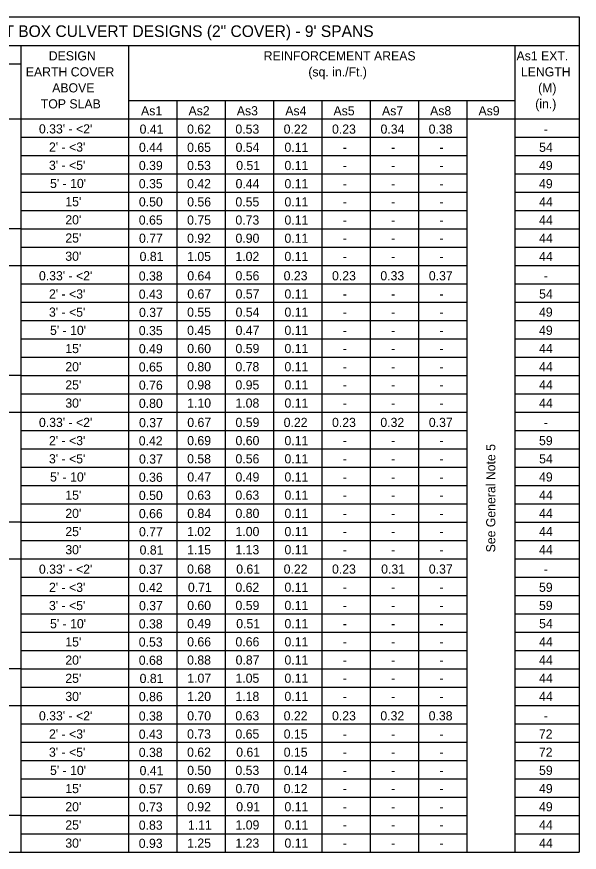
# Model space of a CAD drawing. Extents: x 10346.98 to 10349.19, y 76399.48 to 76400.59.
# Drawn here: x 10347.193 to 10347.579, y 76399.925 to 76400.5 of the extents above; entities that cross this region are included whole.
import ezdxf

# ---------------------------------------------------------------- set-up
doc = ezdxf.new("R2010")
doc.units = 0
doc.layers.add('AdhocPoint_dp', color=7, linetype='Continuous')
doc.layers.add('PlotBorder_dp', color=7, linetype='Continuous')

msp = doc.modelspace()

# ---------------------------------------------------------------- linework, layer by layer
at = {"layer": 'PlotBorder_dp'}
for p, q in [((10346.98451, 76400.49971), (10347.57925, 76400.49971)), ((10347.57925, 76400.49971), (10347.57925, 76399.92549)), ((10346.98451, 76400.47984), (10347.57925, 76400.47984)), ((10347.19559, 76400.47984), (10347.19559, 76399.92549)), ((10347.26947, 76400.47984), (10347.26947, 76399.92549)), ((10347.53506, 76400.47984), (10347.53506, 76399.92549)), ((10347.05314, 76400.46724), (10347.19559, 76400.46724)), ((10347.26947, 76400.44209), (10347.53506, 76400.44209)), ((10347.30267, 76400.44209), (10347.30267, 76399.92549)), ((10347.33586, 76400.44209), (10347.33586, 76399.92549)), ((10347.36906, 76400.44209), (10347.36906, 76399.92549)), ((10347.40226, 76400.44209), (10347.40226, 76399.92549)), ((10347.43546, 76400.44209), (10347.43546, 76399.92549)), ((10347.43546, 76400.44209), (10347.43546, 76399.92549)), ((10347.46866, 76400.44209), (10347.46866, 76399.92549)), ((10347.50186, 76400.44209), (10347.50186, 76399.92549)), ((10346.98451, 76400.42949), (10347.57925, 76400.42949)), ((10347.19559, 76400.41689), (10347.50186, 76400.41689)), ((10347.53506, 76400.41689), (10347.57925, 76400.41689)), ((10347.19559, 76400.40429), (10347.50186, 76400.40429)), ((10347.53506, 76400.40429), (10347.57925, 76400.40429)), ((10347.19559, 76400.39169), (10347.50186, 76400.39169)), ((10347.53506, 76400.39169), (10347.57925, 76400.39169)), ((10347.19559, 76400.37909), (10347.50186, 76400.37909)), ((10347.53506, 76400.37909), (10347.57925, 76400.37909)), ((10347.19559, 76400.36649), (10347.50186, 76400.36649)), ((10347.53506, 76400.36649), (10347.57925, 76400.36649)), ((10347.19559, 76400.35389), (10347.05314, 76400.35389)), ((10347.19559, 76400.35389), (10347.50186, 76400.35389)), ((10347.53506, 76400.35389), (10347.57925, 76400.35389)), ((10347.19559, 76400.34129), (10347.50186, 76400.34129)), ((10347.53506, 76400.34129), (10347.57925, 76400.34129)), ((10346.98451, 76400.32869), (10347.50186, 76400.32869)), ((10347.53506, 76400.32869), (10347.57925, 76400.32869)), ((10347.19559, 76400.31609), (10347.50186, 76400.31609)), ((10347.53506, 76400.31609), (10347.57925, 76400.31609)), ((10347.19559, 76400.30349), (10347.50186, 76400.30349)), ((10347.53506, 76400.30349), (10347.57925, 76400.30349)), ((10347.19559, 76400.29089), (10347.50186, 76400.29089)), ((10347.53506, 76400.29089), (10347.57925, 76400.29089)), ((10347.19559, 76400.27829), (10347.50186, 76400.27829)), ((10347.53506, 76400.27829), (10347.57925, 76400.27829)), ((10347.19559, 76400.26569), (10347.50186, 76400.26569)), ((10347.53506, 76400.26569), (10347.57925, 76400.26569)), ((10347.19559, 76400.25309), (10347.05314, 76400.25309)), ((10347.19559, 76400.25309), (10347.50186, 76400.25309)), ((10347.53506, 76400.25309), (10347.57925, 76400.25309)), ((10347.19559, 76400.24049), (10347.50186, 76400.24049)), ((10347.53506, 76400.24049), (10347.57925, 76400.24049)), ((10346.98451, 76400.22789), (10347.50186, 76400.22789)), ((10347.19621, 76400.22789), (10347.26838, 76400.22789)), ((10347.53506, 76400.22789), (10347.57925, 76400.22789)), ((10347.19559, 76400.21529), (10347.50186, 76400.21529)), ((10347.53506, 76400.21529), (10347.57925, 76400.21529)), ((10347.19559, 76400.20269), (10347.50186, 76400.20269)), ((10347.53506, 76400.20269), (10347.57925, 76400.20269)), ((10347.19559, 76400.19009), (10347.50186, 76400.19009)), ((10347.53506, 76400.19009), (10347.57925, 76400.19009)), ((10347.19559, 76400.17749), (10347.50186, 76400.17749)), ((10347.53506, 76400.17749), (10347.57925, 76400.17749)), ((10347.19559, 76400.16489), (10347.50186, 76400.16489)), ((10347.53506, 76400.16489), (10347.57925, 76400.16489)), ((10347.19559, 76400.15229), (10347.05314, 76400.15229)), ((10347.19559, 76400.15229), (10347.50186, 76400.15229)), ((10347.53506, 76400.15229), (10347.57925, 76400.15229)), ((10347.19559, 76400.13969), (10347.50186, 76400.13969)), ((10347.53506, 76400.13969), (10347.57925, 76400.13969)), ((10346.98451, 76400.12709), (10347.50186, 76400.12709)), ((10347.19621, 76400.12709), (10347.26838, 76400.12709)), ((10347.19621, 76400.12709), (10347.26838, 76400.12709)), ((10347.53506, 76400.12709), (10347.57925, 76400.12709)), ((10347.19559, 76400.11449), (10347.50186, 76400.11449)), ((10347.53506, 76400.11449), (10347.57925, 76400.11449)), ((10347.19559, 76400.10189), (10347.50186, 76400.10189)), ((10347.53506, 76400.10189), (10347.57925, 76400.10189)), ((10347.19559, 76400.08929), (10347.50186, 76400.08929)), ((10347.53506, 76400.08929), (10347.57925, 76400.08929)), ((10347.19559, 76400.07669), (10347.50186, 76400.07669)), ((10347.53506, 76400.07669), (10347.57925, 76400.07669)), ((10347.19559, 76400.06409), (10347.50186, 76400.06409)), ((10347.53506, 76400.06409), (10347.57925, 76400.06409)), ((10347.19559, 76400.05149), (10347.05314, 76400.05149)), ((10347.19559, 76400.05149), (10347.50186, 76400.05149)), ((10347.53506, 76400.05149), (10347.57925, 76400.05149)), ((10347.19559, 76400.03889), (10347.50186, 76400.03889)), ((10347.53506, 76400.03889), (10347.57925, 76400.03889)), ((10346.98451, 76400.02629), (10347.50186, 76400.02629)), ((10347.19621, 76400.02629), (10347.26838, 76400.02629)), ((10347.19621, 76400.02629), (10347.26838, 76400.02629)), ((10347.19621, 76400.02629), (10347.26838, 76400.02629)), ((10347.53506, 76400.02629), (10347.57925, 76400.02629)), ((10347.19559, 76400.01369), (10347.50186, 76400.01369)), ((10347.53506, 76400.01369), (10347.57925, 76400.01369)), ((10347.19559, 76400.00109), (10347.50186, 76400.00109)), ((10347.53506, 76400.00109), (10347.57925, 76400.00109)), ((10347.19559, 76399.98849), (10347.50186, 76399.98849)), ((10347.53506, 76399.98849), (10347.57925, 76399.98849)), ((10347.19559, 76399.97589), (10347.50186, 76399.97589)), ((10347.53506, 76399.97589), (10347.57925, 76399.97589)), ((10347.19559, 76399.96329), (10347.50186, 76399.96329)), ((10347.53506, 76399.96329), (10347.57925, 76399.96329)), ((10347.19559, 76399.95066), (10347.05314, 76399.95066)), ((10347.19559, 76399.95069), (10347.50186, 76399.95069)), ((10347.53506, 76399.95069), (10347.57925, 76399.95069)), ((10347.19559, 76399.93809), (10347.50186, 76399.93809)), ((10347.53506, 76399.93809), (10347.57925, 76399.93809)), ((10346.98451, 76399.92549), (10347.57925, 76399.92549))]:
    msp.add_line(p, q, dxfattribs=at)

# ---------------------------------------------------------------- texts
at = {"layer": 'AdhocPoint_dp'}
for s, height, p in [('TABLE 5 - STANDARD PRECAST BOX CULVERT DESIGNS (2" COVER) - 9\' SPANS', 0.008, (10347.02607, 76400.48578)), ('As1', 0.0063, (10347.27809, 76400.43192)), ('As2', 0.0063, (10347.31072, 76400.43192)), ('As3', 0.0063, (10347.34391, 76400.43192)), ('As4', 0.0063, (10347.37724, 76400.43192)), ('As5', 0.0063, (10347.41034, 76400.43192)), ('As7', 0.0063, (10347.44368, 76400.43192)), ('As8', 0.0063, (10347.47673, 76400.43192)), ('As9', 0.0063, (10347.50998, 76400.43192))]:
    msp.add_text(s, height=height, dxfattribs=at).set_placement(p)
msp.add_text('See General Note 5', height=0.0063, rotation=90, dxfattribs=at).set_placement((10347.52156, 76400.13159))
at = {"layer": 'PlotBorder_dp'}
for s, p in [('DESIGN', (10347.21469, 76400.46968)), ('REINFORCEMENT AREAS', (10347.36237, 76400.46968)), ('(sq. in./Ft.)', (10347.39306, 76400.45868)), ('EARTH COVER', (10347.1989, 76400.45868)), ('ABOVE', (10347.21704, 76400.44768)), ('TOP SLAB', (10347.20921, 76400.43668)), ("0.33' - <2'", (10347.20794, 76400.41948)), ('0.41', (10347.27711, 76400.41932)), ('0.62', (10347.30974, 76400.41932)), ('0.53', (10347.34294, 76400.41932)), ('0.22', (10347.3761, 76400.41932)), ('0.23', (10347.40933, 76400.41932)), ('0.34', (10347.44267, 76400.41932)), ('0.38', (10347.47574, 76400.41932)), ("2' - <3'", (10347.21484, 76400.40698)), ('0.44', (10347.27667, 76400.40682)), ('0.65', (10347.30977, 76400.40682)), ('0.54', (10347.34307, 76400.40682)), ('0.11', (10347.37667, 76400.40682)), ('-', (10347.41673, 76400.40682)), ('-', (10347.44994, 76400.40682)), ('-', (10347.48313, 76400.40682)), ("3' - <5'", (10347.21484, 76400.39448)), ('0.39', (10347.27661, 76400.39432)), ('0.53', (10347.30974, 76400.39432)), ('0.51', (10347.34351, 76400.39432)), ('0.11', (10347.37667, 76400.39432)), ('-', (10347.41673, 76400.39432)), ('-', (10347.44994, 76400.39432)), ('-', (10347.48313, 76400.39432)), ("5' - 10'", (10347.21556, 76400.38198)), ('0.35', (10347.27657, 76400.38182)), ('0.42', (10347.30974, 76400.38182)), ('0.44', (10347.34307, 76400.38182)), ('0.11', (10347.37667, 76400.38182)), ('-', (10347.41673, 76400.38182)), ('-', (10347.44994, 76400.38182)), ('-', (10347.48313, 76400.38182)), ("15'", (10347.22607, 76400.36948)), ('0.50', (10347.27662, 76400.36932)), ('0.56', (10347.30981, 76400.36932)), ('0.55', (10347.34297, 76400.36932)), ('0.11', (10347.37667, 76400.36932)), ('-', (10347.41673, 76400.36932)), ('-', (10347.44994, 76400.36932)), ('-', (10347.48313, 76400.36932)), ("20'", (10347.22607, 76400.35698)), ('0.65', (10347.27657, 76400.35682)), ('0.75', (10347.30977, 76400.35682)), ('0.73', (10347.34294, 76400.35682)), ('0.11', (10347.37667, 76400.35682)), ('-', (10347.41673, 76400.35682)), ('-', (10347.44994, 76400.35682)), ('-', (10347.48313, 76400.35682)), ("25'", (10347.22607, 76400.34448)), ('0.77', (10347.27669, 76400.34432)), ('0.92', (10347.30974, 76400.34432)), ('0.90', (10347.34302, 76400.34432)), ('0.11', (10347.37667, 76400.34432)), ('-', (10347.41673, 76400.34432)), ('-', (10347.44994, 76400.34432)), ('-', (10347.48313, 76400.34432)), ("30'", (10347.22607, 76400.33198)), ('0.81', (10347.27711, 76400.33182)), ('1.05', (10347.30977, 76400.33182)), ('1.02', (10347.34294, 76400.33182)), ('0.11', (10347.37667, 76400.33182)), ('-', (10347.41673, 76400.33182)), ('-', (10347.44994, 76400.33182)), ('-', (10347.48313, 76400.33182)), ("0.33' - <2'", (10347.20794, 76400.31854)), ('0.38', (10347.27656, 76400.31838)), ('0.64', (10347.30987, 76400.31854)), ('0.56', (10347.34301, 76400.31854)), ('0.23', (10347.37609, 76400.31854)), ('0.23', (10347.40933, 76400.31854)), ('0.33', (10347.44254, 76400.31854)), ('0.37', (10347.47587, 76400.31854)), ('-', (10347.55483, 76400.31854)), ("2' - <3'", (10347.21484, 76400.30604)), ('0.43', (10347.27654, 76400.30588)), ('0.67', (10347.30988, 76400.30604)), ('0.57', (10347.34308, 76400.30604)), ('0.11', (10347.37667, 76400.30604)), ('54', (10347.55163, 76400.30604)), ('-', (10347.41673, 76400.30604)), ('-', (10347.44994, 76400.30604)), ('-', (10347.48313, 76400.30604)), ("3' - <5'", (10347.21484, 76400.29354)), ('0.37', (10347.27669, 76400.29338)), ('0.55', (10347.30977, 76400.29354)), ('0.54', (10347.34307, 76400.29354)), ('0.11', (10347.37667, 76400.29354)), ('49', (10347.55157, 76400.29354)), ('-', (10347.41673, 76400.29354)), ('-', (10347.44994, 76400.29354)), ('-', (10347.48313, 76400.29354)), ("5' - 10'", (10347.21556, 76400.28104)), ('0.35', (10347.27657, 76400.28088)), ('0.45', (10347.30977, 76400.28104)), ('0.47', (10347.34308, 76400.28104)), ('0.11', (10347.37667, 76400.28104)), ('49', (10347.55157, 76400.28104)), ('-', (10347.41673, 76400.28104)), ('-', (10347.44994, 76400.28104)), ('-', (10347.48313, 76400.28104)), ("15'", (10347.22607, 76400.26854)), ('0.49', (10347.27661, 76400.26838)), ('0.60', (10347.30982, 76400.26854)), ('0.59', (10347.34301, 76400.26854)), ('0.11', (10347.37667, 76400.26854)), ('-', (10347.41673, 76400.26854)), ('-', (10347.44994, 76400.26854)), ('-', (10347.48313, 76400.26854)), ('44', (10347.55163, 76400.26854)), ("20'", (10347.22607, 76400.25604)), ('0.65', (10347.27657, 76400.25588)), ('0.80', (10347.30982, 76400.25604)), ('0.78', (10347.34296, 76400.25604)), ('0.11', (10347.37667, 76400.25604)), ('-', (10347.41673, 76400.25604)), ('-', (10347.44994, 76400.25604)), ('-', (10347.48313, 76400.25604)), ('44', (10347.55163, 76400.25604)), ("25'", (10347.22607, 76400.24354)), ('0.76', (10347.27661, 76400.24338)), ('0.98', (10347.30976, 76400.24354)), ('0.95', (10347.34297, 76400.24354)), ('0.11', (10347.37667, 76400.24354)), ('44', (10347.55163, 76400.24354)), ('-', (10347.41673, 76400.24354)), ('-', (10347.44994, 76400.24354)), ('-', (10347.48313, 76400.24354)), ("30'", (10347.22607, 76400.23104)), ('0.80', (10347.27662, 76400.23088)), ('1.10', (10347.30982, 76400.23104)), ('1.08', (10347.34296, 76400.23104)), ('0.11', (10347.37667, 76400.23104)), ('44', (10347.55163, 76400.23104)), ('-', (10347.41673, 76400.23104)), ('-', (10347.44994, 76400.23104)), ('-', (10347.48313, 76400.23104)), ("0.33' - <2'", (10347.20794, 76400.21776)), ('0.67', (10347.30988, 76400.21776)), ('0.59', (10347.34301, 76400.21776)), ('0.22', (10347.3761, 76400.21776)), ('0.23', (10347.40933, 76400.21776)), ('0.32', (10347.44254, 76400.21776)), ('0.37', (10347.47587, 76400.21776)), ('0.37', (10347.27669, 76400.2176)), ('-', (10347.55483, 76400.21776)), ("2' - <3'", (10347.21484, 76400.20526)), ('0.42', (10347.27654, 76400.2051)), ('0.69', (10347.30981, 76400.20526)), ('0.60', (10347.34302, 76400.20526)), ('0.11', (10347.37667, 76400.20526)), ('-', (10347.41673, 76400.20526)), ('-', (10347.44994, 76400.20526)), ('-', (10347.48313, 76400.20526)), ('59', (10347.55157, 76400.20526)), ("3' - <5'", (10347.21484, 76400.19276)), ('0.37', (10347.27669, 76400.1926)), ('0.58', (10347.30976, 76400.19276)), ('0.56', (10347.34301, 76400.19276)), ('0.11', (10347.37667, 76400.19276)), ('-', (10347.41673, 76400.19276)), ('-', (10347.44994, 76400.19276)), ('-', (10347.48313, 76400.19276)), ('54', (10347.55163, 76400.19276)), ("5' - 10'", (10347.21556, 76400.18026)), ('0.36', (10347.27661, 76400.1801)), ('0.47', (10347.30988, 76400.18026)), ('0.49', (10347.34301, 76400.18026)), ('0.11', (10347.37667, 76400.18026)), ('49', (10347.55157, 76400.18026)), ('-', (10347.41673, 76400.18026)), ('-', (10347.44994, 76400.18026)), ('-', (10347.48313, 76400.18026)), ("15'", (10347.22607, 76400.16776)), ('0.50', (10347.27662, 76400.1676)), ('0.63', (10347.30974, 76400.16776)), ('0.63', (10347.34294, 76400.16776)), ('0.11', (10347.37667, 76400.16776)), ('44', (10347.55163, 76400.16776)), ('-', (10347.41673, 76400.16776)), ('-', (10347.44994, 76400.16776)), ('-', (10347.48313, 76400.16776)), ("20'", (10347.22607, 76400.15526)), ('0.66', (10347.27661, 76400.1551)), ('0.84', (10347.30987, 76400.15526)), ('0.80', (10347.34302, 76400.15526)), ('0.11', (10347.37667, 76400.15526)), ('44', (10347.55163, 76400.15526)), ('-', (10347.41673, 76400.15526)), ('-', (10347.44994, 76400.15526)), ('-', (10347.48313, 76400.15526)), ("25'", (10347.22607, 76400.14276)), ('0.77', (10347.27669, 76400.1426)), ('1.02', (10347.30974, 76400.14276)), ('1.00', (10347.34302, 76400.14276)), ('0.11', (10347.37667, 76400.14276)), ('-', (10347.41673, 76400.14276)), ('-', (10347.44994, 76400.14276)), ('-', (10347.48313, 76400.14276)), ('44', (10347.55163, 76400.14276)), ("30'", (10347.22607, 76400.13026)), ('0.81', (10347.27711, 76400.1301)), ('1.15', (10347.30977, 76400.13026)), ('1.13', (10347.34294, 76400.13026)), ('0.11', (10347.37667, 76400.13026)), ('-', (10347.41673, 76400.13026)), ('-', (10347.44994, 76400.13026)), ('-', (10347.48313, 76400.13026)), ('44', (10347.55163, 76400.13026)), ("0.33' - <2'", (10347.20794, 76400.11692)), ('0.37', (10347.27669, 76400.11682)), ('0.68', (10347.30976, 76400.11698)), ('0.61', (10347.34351, 76400.11698)), ('0.22', (10347.3761, 76400.11698)), ('0.23', (10347.40933, 76400.11698)), ('0.31', (10347.44311, 76400.11698)), ('0.37', (10347.47587, 76400.11698)), ('-', (10347.55483, 76400.11698)), ("2' - <3'", (10347.21484, 76400.10442)), ('0.42', (10347.27654, 76400.10432)), ('0.71', (10347.31031, 76400.10448)), ('0.62', (10347.34294, 76400.10448)), ('0.11', (10347.37667, 76400.10448)), ('59', (10347.55157, 76400.10448)), ('-', (10347.41673, 76400.10448)), ('-', (10347.44994, 76400.10448)), ('-', (10347.48313, 76400.10448)), ("3' - <5'", (10347.21484, 76400.09192)), ('0.37', (10347.27669, 76400.09182)), ('0.60', (10347.30982, 76400.09198)), ('0.59', (10347.34301, 76400.09198)), ('0.11', (10347.37667, 76400.09198)), ('59', (10347.55157, 76400.09198)), ('-', (10347.41673, 76400.09198)), ('-', (10347.44994, 76400.09198)), ('-', (10347.48313, 76400.09198)), ("5' - 10'", (10347.21556, 76400.07942)), ('0.38', (10347.27656, 76400.07932)), ('0.49', (10347.30981, 76400.07948)), ('0.51', (10347.34351, 76400.07948)), ('0.11', (10347.37667, 76400.07948)), ('-', (10347.41673, 76400.07948)), ('-', (10347.44994, 76400.07948)), ('-', (10347.48313, 76400.07948)), ('54', (10347.55163, 76400.07948)), ("15'", (10347.22607, 76400.06692)), ('0.53', (10347.27654, 76400.06682)), ('0.66', (10347.30981, 76400.06698)), ('0.66', (10347.34301, 76400.06698)), ('0.11', (10347.37667, 76400.06698)), ('-', (10347.41673, 76400.06698)), ('-', (10347.44994, 76400.06698)), ('-', (10347.48313, 76400.06698)), ('44', (10347.55163, 76400.06698)), ("20'", (10347.22607, 76400.05442)), ('0.68', (10347.27656, 76400.05432)), ('0.88', (10347.30976, 76400.05448)), ('0.87', (10347.34308, 76400.05448)), ('0.11', (10347.37667, 76400.05448)), ('44', (10347.55163, 76400.05448)), ('-', (10347.41673, 76400.05448)), ('-', (10347.44994, 76400.05448)), ('-', (10347.48313, 76400.05448)), ("25'", (10347.22607, 76400.04192)), ('0.81', (10347.27711, 76400.04182)), ('1.07', (10347.30988, 76400.04198)), ('1.05', (10347.34297, 76400.04198)), ('0.11', (10347.37667, 76400.04198)), ('44', (10347.55163, 76400.04198)), ('-', (10347.41673, 76400.04198)), ('-', (10347.44994, 76400.04198)), ('-', (10347.48313, 76400.04198)), ("30'", (10347.22607, 76400.02942)), ('0.86', (10347.27661, 76400.02932)), ('1.20', (10347.30982, 76400.02948)), ('1.18', (10347.34296, 76400.02948)), ('0.11', (10347.37667, 76400.02948)), ('44', (10347.55163, 76400.02948)), ('-', (10347.41673, 76400.02948)), ('-', (10347.44994, 76400.02948)), ('-', (10347.48313, 76400.02948)), ("0.33' - <2'", (10347.20794, 76400.01614)), ('0.38', (10347.27656, 76400.01599)), ('0.70', (10347.30982, 76400.01614)), ('0.63', (10347.34294, 76400.01614)), ('0.22', (10347.3761, 76400.01614)), ('0.23', (10347.40933, 76400.01614)), ('0.32', (10347.44254, 76400.01614)), ('0.38', (10347.47574, 76400.01614)), ('-', (10347.55483, 76400.01614)), ("2' - <3'", (10347.21484, 76400.00364)), ('0.43', (10347.27654, 76400.00349)), ('0.73', (10347.30974, 76400.00364)), ('0.65', (10347.34297, 76400.00364)), ('0.15', (10347.37612, 76400.00364)), ('-', (10347.41673, 76400.00364)), ('-', (10347.44994, 76400.00364)), ('-', (10347.48313, 76400.00364)), ('72', (10347.5515, 76400.00364)), ("3' - <5'", (10347.21484, 76399.99114)), ('0.38', (10347.27656, 76399.99099)), ('0.62', (10347.30974, 76399.99114)), ('0.61', (10347.34351, 76399.99114)), ('0.15', (10347.37612, 76399.99114)), ('72', (10347.5515, 76399.99114)), ('-', (10347.41673, 76399.99114)), ('-', (10347.44994, 76399.99114)), ('-', (10347.48313, 76399.99114)), ("5' - 10'", (10347.21556, 76399.97864)), ('0.41', (10347.27711, 76399.97849)), ('0.50', (10347.30982, 76399.97864)), ('0.53', (10347.34294, 76399.97864)), ('0.14', (10347.37622, 76399.97864)), ('59', (10347.55157, 76399.97864)), ('-', (10347.41673, 76399.97864)), ('-', (10347.44994, 76399.97864)), ('-', (10347.48313, 76399.97864)), ("15'", (10347.22607, 76399.96614)), ('0.57', (10347.27669, 76399.96599)), ('0.69', (10347.30981, 76399.96614)), ('0.70', (10347.34302, 76399.96614)), ('0.12', (10347.3761, 76399.96614)), ('49', (10347.55157, 76399.96614)), ('-', (10347.41673, 76399.96614)), ('-', (10347.44994, 76399.96614)), ('-', (10347.48313, 76399.96614)), ("20'", (10347.22607, 76399.95364)), ('0.92', (10347.30974, 76399.95364)), ('0.91', (10347.34351, 76399.95364)), ('0.11', (10347.37667, 76399.95364)), ('49', (10347.55157, 76399.95364)), ('0.73', (10347.27654, 76399.95349)), ('-', (10347.41673, 76399.95364)), ('-', (10347.44994, 76399.95364)), ('-', (10347.48313, 76399.95364)), ("25'", (10347.22607, 76399.94114)), ('0.83', (10347.27654, 76399.94099)), ('1.11', (10347.31031, 76399.94114)), ('1.09', (10347.34301, 76399.94114)), ('0.11', (10347.37667, 76399.94114)), ('-', (10347.41673, 76399.94114)), ('-', (10347.44994, 76399.94114)), ('-', (10347.48313, 76399.94114)), ('44', (10347.55163, 76399.94114)), ("30'", (10347.22607, 76399.92864)), ('0.93', (10347.27654, 76399.92849)), ('1.25', (10347.30977, 76399.92864)), ('1.23', (10347.34294, 76399.92864)), ('0.11', (10347.37667, 76399.92864)), ('-', (10347.41673, 76399.92864)), ('-', (10347.44994, 76399.92864)), ('-', (10347.48313, 76399.92864)), ('44', (10347.55163, 76399.92864))]:
    msp.add_text(s, height=0.0063, dxfattribs=at).set_placement(p)
for s, p in [('As1 EXT.', (10347.5361, 76400.46968)), ('LENGTH', (10347.53913, 76400.45868)), ('(M)', (10347.55093, 76400.44768)), ('(in.)', (10347.54897, 76400.43668)), ('-', (10347.55483, 76400.41932)), ('54', (10347.55163, 76400.40682)), ('49', (10347.55157, 76400.39432)), ('49', (10347.55157, 76400.38182)), ('44', (10347.55163, 76400.36932)), ('44', (10347.55163, 76400.35682)), ('44', (10347.55163, 76400.34432)), ('44', (10347.55163, 76400.33182))]:
    msp.add_text(s, height=0.0063, rotation=360, dxfattribs=at).set_placement(p)

doc.saveas('drawing.dxf')
